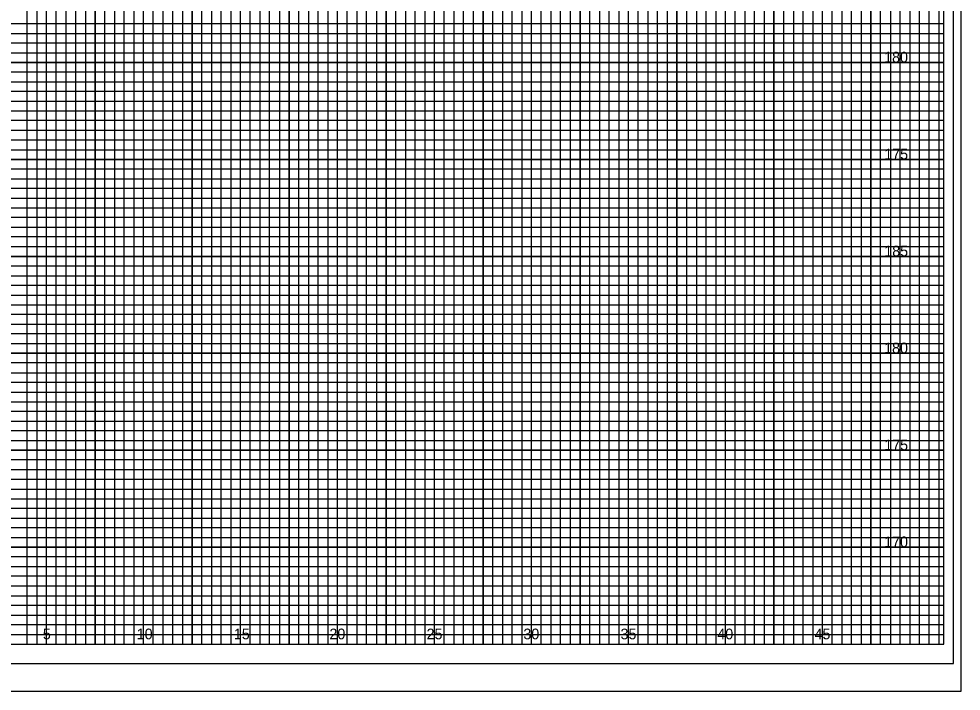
# Model space of a CAD drawing. Extents: x -4 to 103, y -2 to 138.
# Drawn here: x 54.82 to 103.4, y -2.43 to 32.25 of the extents above; entities that cross this region are included whole.
import ezdxf

# ---------------------------------------------------------------- set-up
doc = ezdxf.new("R2010")
doc.units = 0
for name, color, linetype in [('Old_Level_10', 7, 'Continuous'), ('Old_Level_3', 7, 'Continuous'), ('Old_Level_4', 7, 'Continuous'), ('Old_Level_5', 7, 'Continuous'), ('Old_Level_8', 7, 'Continuous'), ('Prop XS Elevation Labels', 7, 'Continuous'), ('Prop XS EOT Tick Mark', 7, 'Continuous'), ('Prop XS Finish Grade', 7, 'Continuous'), ('Prop XS Finish Grade Pavement', 7, 'Continuous')]:
    doc.layers.add(name, color=color, linetype=linetype)

msp = doc.modelspace()

# ---------------------------------------------------------------- linework, layer by layer
at = {"layer": 'Old_Level_10'}
for p, q in [((56.25, 0), (56.25, 65)), ((58.75, 0), (58.75, 65)), ((61.25, 0), (61.25, 65)), ((63.75, 0), (63.75, 65)), ((66.25, 0), (66.25, 65)), ((68.75, 0), (68.75, 65)), ((71.25, 0), (71.25, 65)), ((73.75, 0), (73.75, 65)), ((91.25, 0), (91.25, 63.425)), ((93.75, 0), (93.75, 63.425)), ((96.25, 0), (96.25, 63.425)), ((98.75, 0), (98.75, 63.425)), ((101.25, 0), (101.25, 63.425)), ((76.25, 0), (76.25, 62)), ((78.75, 0), (78.75, 62)), ((81.25, 0), (81.25, 62)), ((83.75, 0), (83.75, 62)), ((86.25, 0), (86.25, 62)), ((88.75, 0), (88.75, 62)), ((0, 30), (102.5, 30)), ((0, 27.5), (102.5, 27.5)), ((0, 25), (102.5, 25)), ((0, 22.5), (102.5, 22.5)), ((0, 20), (102.5, 20)), ((0, 17.5), (102.5, 17.5)), ((0, 15), (102.5, 15)), ((0, 12.5), (102.5, 12.5)), ((0, 10), (102.5, 10)), ((0, 7.5), (102.5, 7.5)), ((0, 5), (102.5, 5)), ((0, 2.5), (102.5, 2.5))]:
    msp.add_line(p, q, dxfattribs=at)
at = {"layer": 'Old_Level_3'}
msp.add_line((-3.5, -2.425), (103.4, -2.425), dxfattribs=at)
at = {"layer": 'Old_Level_4'}
msp.add_lwpolyline([(103, 66), (-2.8, 66), (-2.8, -1), (103, -1)], close=True, dxfattribs=at)
at = {"layer": 'Old_Level_5'}
msp.add_lwpolyline([(103.4, 67.4), (-3.5, 67.4), (-3.5, -2.425), (103.4, -2.425)], close=True, dxfattribs=at)
at = {"layer": 'Old_Level_8'}
for points in [[(56.25, 0), (56.25, 65)], [(58.75, 65), (58.75, 0), (61.25, 0), (61.25, 65)], [(63.75, 65), (63.75, 0), (66.25, 0), (66.25, 65)], [(68.75, 65), (68.75, 0), (71.25, 0), (71.25, 65)], [(73.75, 65), (73.75, 0), (76.25, 0), (76.25, 62)], [(88.75, 62), (88.75, 0), (91.25, 0), (91.25, 63.425)], [(93.75, 63.425), (93.75, 0), (96.25, 0), (96.25, 63.425)], [(98.75, 63.425), (98.75, 0), (101.25, 0), (101.25, 63.425)], [(78.75, 62), (78.75, 0), (81.25, 0), (81.25, 62)], [(83.75, 62), (83.75, 0), (86.25, 0), (86.25, 62)], [(0, 27.5), (102.5, 27.5), (102.5, 30), (0, 30)], [(0, 22.5), (102.5, 22.5), (102.5, 25), (0, 25)], [(0, 17.5), (102.5, 17.5), (102.5, 20), (0, 20)], [(0, 12.5), (102.5, 12.5), (102.5, 15), (0, 15)], [(0, 7.5), (102.5, 7.5), (102.5, 10), (0, 10)], [(0, 2.5), (102.5, 2.5), (102.5, 5), (0, 5)]]:
    msp.add_lwpolyline(points, dxfattribs=at)
at = {"layer": 'Prop XS Elevation Labels'}
msp.add_lwpolyline([(102.5, 65), (0, 65), (0, 0), (102.5, 0)], close=True, dxfattribs=at)
at = {"layer": 'Prop XS Finish Grade'}
for points in [[(54.75, 0), (55.25, 0), (55.25, 65)], [(55.75, 65), (55.75, 0), (56.75, 0), (56.75, 65)], [(57.25, 65), (57.25, 0), (57.75, 0), (57.75, 65)], [(58.25, 65), (58.25, 0), (59.25, 0), (59.25, 65)], [(59.75, 65), (59.75, 0), (60.25, 0), (60.25, 65)], [(60.75, 65), (60.75, 0), (61.75, 0), (61.75, 65)], [(62.25, 65), (62.25, 0), (62.75, 0), (62.75, 65)], [(63.25, 65), (63.25, 0), (64.25, 0), (64.25, 65)], [(64.75, 65), (64.75, 0), (65.25, 0), (65.25, 65)], [(65.75, 65), (65.75, 0), (66.75, 0), (66.75, 65)], [(67.25, 65), (67.25, 0), (67.75, 0), (67.75, 65)], [(68.25, 65), (68.25, 0), (69.25, 0), (69.25, 65)], [(69.75, 65), (69.75, 0), (70.25, 0), (70.25, 65)], [(70.75, 65), (70.75, 0), (71.75, 0), (71.75, 65)], [(72.25, 65), (72.25, 0), (72.75, 0), (72.75, 65)], [(73.25, 65), (73.25, 0), (74.25, 0), (74.25, 62)], [(89.75, 62), (89.75, 0), (90.25, 0), (90.25, 63.425)], [(90.75, 63.425), (90.75, 0), (91.75, 0), (91.75, 63.425)], [(92.25, 63.425), (92.25, 0), (92.75, 0), (92.75, 63.425)], [(93.25, 63.425), (93.25, 0), (94.25, 0), (94.25, 63.425)], [(94.75, 63.425), (94.75, 0), (95.25, 0), (95.25, 63.425)], [(95.75, 63.425), (95.75, 0), (96.75, 0), (96.75, 63.425)], [(97.25, 63.425), (97.25, 0), (97.75, 0), (97.75, 63.425)], [(98.25, 63.425), (98.25, 0), (99.25, 0), (99.25, 63.425)], [(99.75, 63.425), (99.75, 0), (100.25, 0), (100.25, 63.425)], [(100.25, 63.425), (100.75, 63.425), (100.75, 0), (101.75, 0), (101.75, 63.425), (102.25, 63.425), (102.25, 0)], [(74.75, 62), (74.75, 0), (75.25, 0), (75.25, 62)], [(75.75, 62), (75.75, 0), (76.75, 0), (76.75, 62)], [(77.25, 62), (77.25, 0), (77.75, 0), (77.75, 62)], [(78.25, 62), (78.25, 0), (79.25, 0), (79.25, 62)], [(79.75, 62), (79.75, 0), (80.25, 0), (80.25, 62)], [(80.75, 62), (80.75, 0), (81.75, 0), (81.75, 62)], [(82.25, 62), (82.25, 0), (82.75, 0), (82.75, 62)], [(83.25, 62), (83.25, 0), (84.25, 0), (84.25, 62)], [(84.75, 62), (84.75, 0), (85.25, 0), (85.25, 62)], [(85.75, 62), (85.75, 0), (86.75, 0), (86.75, 62)], [(87.25, 62), (87.25, 0), (87.75, 0), (87.75, 62)], [(88.25, 62), (88.25, 0), (89.25, 0), (89.25, 62)], [(0, 31.5), (102.5, 31.5), (102.5, 32), (0, 32)], [(0, 30.5), (102.5, 30.5), (102.5, 31), (0, 31)], [(0, 29), (102.5, 29), (102.5, 29.5), (0, 29.5)], [(0, 28), (102.5, 28), (102.5, 28.5), (0, 28.5)], [(0, 26.5), (102.5, 26.5), (102.5, 27), (0, 27)], [(0, 25.5), (102.5, 25.5), (102.5, 26), (0, 26)], [(0, 24), (102.5, 24), (102.5, 24.5), (0, 24.5)], [(0, 23), (102.5, 23), (102.5, 23.5), (0, 23.5)], [(0, 21.5), (102.5, 21.5), (102.5, 22), (0, 22)], [(0, 20.5), (102.5, 20.5), (102.5, 21), (0, 21)], [(0, 19), (102.5, 19), (102.5, 19.5), (0, 19.5)], [(0, 18), (102.5, 18), (102.5, 18.5), (0, 18.5)], [(0, 16.5), (102.5, 16.5), (102.5, 17), (0, 17)], [(0, 15.5), (102.5, 15.5), (102.5, 16), (0, 16)], [(0, 14), (102.5, 14), (102.5, 14.5), (0, 14.5)], [(0, 13), (102.5, 13), (102.5, 13.5), (0, 13.5)], [(0, 11.5), (102.5, 11.5), (102.5, 12), (0, 12)], [(0, 10.5), (102.5, 10.5), (102.5, 11), (0, 11)], [(0, 9), (102.5, 9), (102.5, 9.5), (0, 9.5)], [(0, 8), (102.5, 8), (102.5, 8.5), (0, 8.5)], [(0, 6.5), (102.5, 6.5), (102.5, 7), (0, 7)], [(0, 5.5), (102.5, 5.5), (102.5, 6), (0, 6)], [(0, 4), (102.5, 4), (102.5, 4.5), (0, 4.5)], [(0, 3), (102.5, 3), (102.5, 3.5), (0, 3.5)], [(0, 1.5), (102.5, 1.5), (102.5, 2), (0, 2)], [(0, 0.5), (102.5, 0.5), (102.5, 1), (0, 1)]]:
    msp.add_lwpolyline(points, dxfattribs=at)

# ---------------------------------------------------------------- texts
at = {"layer": 'Prop XS EOT Tick Mark'}
for s, p in [('180', (99.43, 30)), ('175', (99.438, 25)), ('185', (99.438, 20)), ('180', (99.43, 15)), ('175', (99.438, 10)), ('170', (99.43, 5))]:
    msp.add_text(s, height=0.55, dxfattribs=at).set_placement(p)
at = {"layer": 'Prop XS Finish Grade Pavement'}
for s, p in [('5', (56.057, 0.25)), ('10', (60.897, 0.25)), ('15', (65.906, 0.25)), ('20', (70.831, 0.25)), ('25', (75.84, 0.25)), ('30', (80.831, 0.25)), ('35', (85.84, 0.25)), ('40', (90.831, 0.25)), ('45', (95.84, 0.25))]:
    msp.add_text(s, height=0.55, dxfattribs=at).set_placement(p)

doc.saveas('drawing.dxf')
